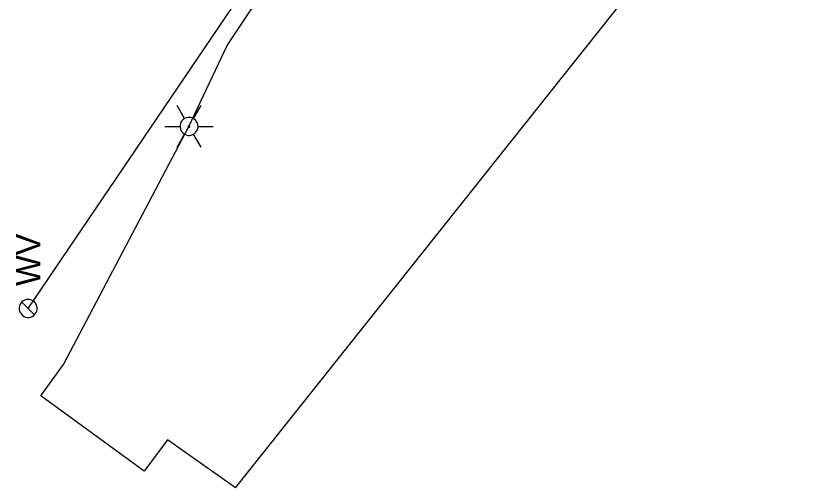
# Model space of a CAD drawing. Extents: x 596028 to 606371, y 330010 to 403088.
# Drawn here: x 604660.9 to 604787.9, y 330748.3 to 330823.2 of the extents above; entities that cross this region are included whole.
import ezdxf

# ---------------------------------------------------------------- set-up
doc = ezdxf.new("R2010")
doc.units = 0
for name, color, linetype in [('E_LTG', 7, 'Continuous'), ('E_UTL_E_UG', 7, 'Continuous'), ('E_UTL_W', 7, 'Continuous'), ('E_UTL_W_UG', 7, 'Continuous')]:
    doc.layers.add(name, color=color, linetype=linetype)

msp = doc.modelspace()

# ---------------------------------------------------------------- linework, layer by layer
at = {"layer": 'E_LTG'}
for points in [[(604687.64, 330806.89), (604686.45, 330808.95)], [(604689.07, 330806.89), (604690.26, 330808.95)], [(604689.78, 330805.65), (604689.75, 330805.92), (604689.68, 330806.18), (604689.55, 330806.42), (604689.38, 330806.63), (604689.18, 330806.81), (604688.94, 330806.95), (604688.69, 330807.04), (604688.42, 330807.08), (604688.15, 330807.06), (604687.88, 330807), (604687.64, 330806.89), (604687.41, 330806.73), (604687.23, 330806.53), (604687.08, 330806.3), (604686.98, 330806.05), (604686.93, 330805.78), (604686.93, 330805.51), (604686.98, 330805.25), (604687.08, 330804.99), (604687.23, 330804.77), (604687.41, 330804.57), (604687.64, 330804.41), (604687.88, 330804.3), (604688.15, 330804.23), (604688.42, 330804.22), (604688.69, 330804.26), (604688.94, 330804.35), (604689.18, 330804.48), (604689.38, 330804.66), (604689.55, 330804.88), (604689.68, 330805.12), (604689.75, 330805.38), (604689.78, 330805.65)], [(604689.78, 330805.65), (604689.75, 330805.92), (604689.68, 330806.18), (604689.55, 330806.42), (604689.38, 330806.63), (604689.18, 330806.81), (604688.94, 330806.95), (604688.69, 330807.04), (604688.42, 330807.08), (604688.15, 330807.06), (604687.88, 330807), (604687.64, 330806.89), (604687.41, 330806.73), (604687.23, 330806.53), (604687.08, 330806.3), (604686.98, 330806.05), (604686.93, 330805.78), (604686.93, 330805.51), (604686.98, 330805.25), (604687.08, 330804.99), (604687.23, 330804.77), (604687.41, 330804.57), (604687.64, 330804.41), (604687.88, 330804.3), (604688.15, 330804.23), (604688.42, 330804.22), (604688.69, 330804.26), (604688.94, 330804.35), (604689.18, 330804.48), (604689.38, 330804.66), (604689.55, 330804.88), (604689.68, 330805.12), (604689.75, 330805.38), (604689.78, 330805.65)], [(604689.78, 330805.65), (604689.75, 330805.92), (604689.68, 330806.18), (604689.55, 330806.42), (604689.38, 330806.63), (604689.18, 330806.81), (604688.94, 330806.95), (604688.69, 330807.04), (604688.42, 330807.08), (604688.15, 330807.06), (604687.88, 330807), (604687.64, 330806.89), (604687.41, 330806.73), (604687.23, 330806.53), (604687.08, 330806.3), (604686.98, 330806.05), (604686.93, 330805.78), (604686.93, 330805.51), (604686.98, 330805.25), (604687.08, 330804.99), (604687.23, 330804.77), (604687.41, 330804.57), (604687.64, 330804.41), (604687.88, 330804.3), (604688.15, 330804.23), (604688.42, 330804.22), (604688.69, 330804.26), (604688.94, 330804.35), (604689.18, 330804.48), (604689.38, 330804.66), (604689.55, 330804.88), (604689.68, 330805.12), (604689.75, 330805.38), (604689.78, 330805.65)], [(604684.54, 330805.65), (604686.92, 330805.65)], [(604688.47, 330805.65), (604688.47, 330805.67), (604688.46, 330805.69), (604688.45, 330805.71), (604688.44, 330805.73), (604688.42, 330805.75), (604688.4, 330805.76), (604688.38, 330805.76), (604688.36, 330805.77), (604688.33, 330805.77), (604688.31, 330805.76), (604688.29, 330805.75), (604688.27, 330805.74), (604688.26, 330805.72), (604688.24, 330805.7), (604688.24, 330805.68), (604688.23, 330805.66), (604688.23, 330805.64), (604688.24, 330805.61), (604688.24, 330805.59), (604688.26, 330805.57), (604688.27, 330805.56), (604688.29, 330805.55), (604688.31, 330805.54), (604688.33, 330805.53), (604688.36, 330805.53), (604688.38, 330805.53), (604688.4, 330805.54), (604688.42, 330805.55), (604688.44, 330805.57), (604688.45, 330805.58), (604688.46, 330805.6), (604688.47, 330805.63), (604688.47, 330805.65)], [(604689.78, 330805.65), (604692.16, 330805.65)], [(604686.45, 330802.35), (604687.64, 330804.41)], [(604690.26, 330802.35), (604689.07, 330804.41)]]:
    msp.add_lwpolyline(points, dxfattribs=at)
at = {"layer": 'E_UTL_E_UG'}
for points in [[(604695.73, 330748.29), (604684.95, 330755.93), (604681.24, 330750.97), (604664.85, 330762.93), (604668.47, 330767.86), (604688.35, 330805.65), (604694.41, 330818.48), (604703.37, 330832.03), (604758.06, 330920.64), (604761.47, 330923.51), (604832.36, 331051.66)], [(604695.73, 330748.29), (604761.4, 330830.97), (604799.82, 330903.8), (604805.91, 330901.32)]]:
    msp.add_lwpolyline(points, dxfattribs=at)
at = {"layer": 'E_UTL_W'}
for points in [[(604662.85, 330778.2), (604662.58, 330778.18), (604662.32, 330778.1), (604662.08, 330777.98), (604661.87, 330777.81), (604661.69, 330777.61), (604661.55, 330777.37), (604661.46, 330777.11), (604661.43, 330776.85), (604661.44, 330776.58), (604661.5, 330776.31), (604661.62, 330776.07), (604661.77, 330775.84), (604661.97, 330775.66), (604662.2, 330775.51), (604662.45, 330775.41), (604662.71, 330775.36), (604662.99, 330775.36), (604663.25, 330775.41), (604663.5, 330775.51), (604663.73, 330775.66), (604663.93, 330775.84), (604664.09, 330776.07), (604664.2, 330776.31), (604664.26, 330776.58), (604664.27, 330776.85), (604664.24, 330777.11), (604664.15, 330777.37), (604664.01, 330777.61), (604663.83, 330777.81), (604663.62, 330777.98), (604663.38, 330778.1), (604663.12, 330778.18), (604662.85, 330778.2)], [(604663.86, 330775.77), (604661.84, 330777.79)]]:
    msp.add_lwpolyline(points, dxfattribs=at)
at = {"layer": 'E_UTL_W_UG'}
msp.add_lwpolyline([(604662.85, 330776.78), (604719.99, 330861.17), (604771.51, 330900.13), (604792.62, 330926.22), (604804.59, 330947.13), (605054.68, 331381.7), (605055.13, 331442.45), (605044.65, 331474.36), (605047.01, 331851.63), (605038.36, 332278.66), (605035.8, 332410.28), (605072.23, 332411.32), (605076.98, 332411.12), (605079.88, 332411.16)], dxfattribs=at)

# ---------------------------------------------------------------- texts
at = {"layer": 'E_UTL_W'}
msp.add_text('WV', height=3.85, rotation=90, dxfattribs=at).set_placement((604664.78, 330780.34))

doc.saveas('drawing.dxf')
